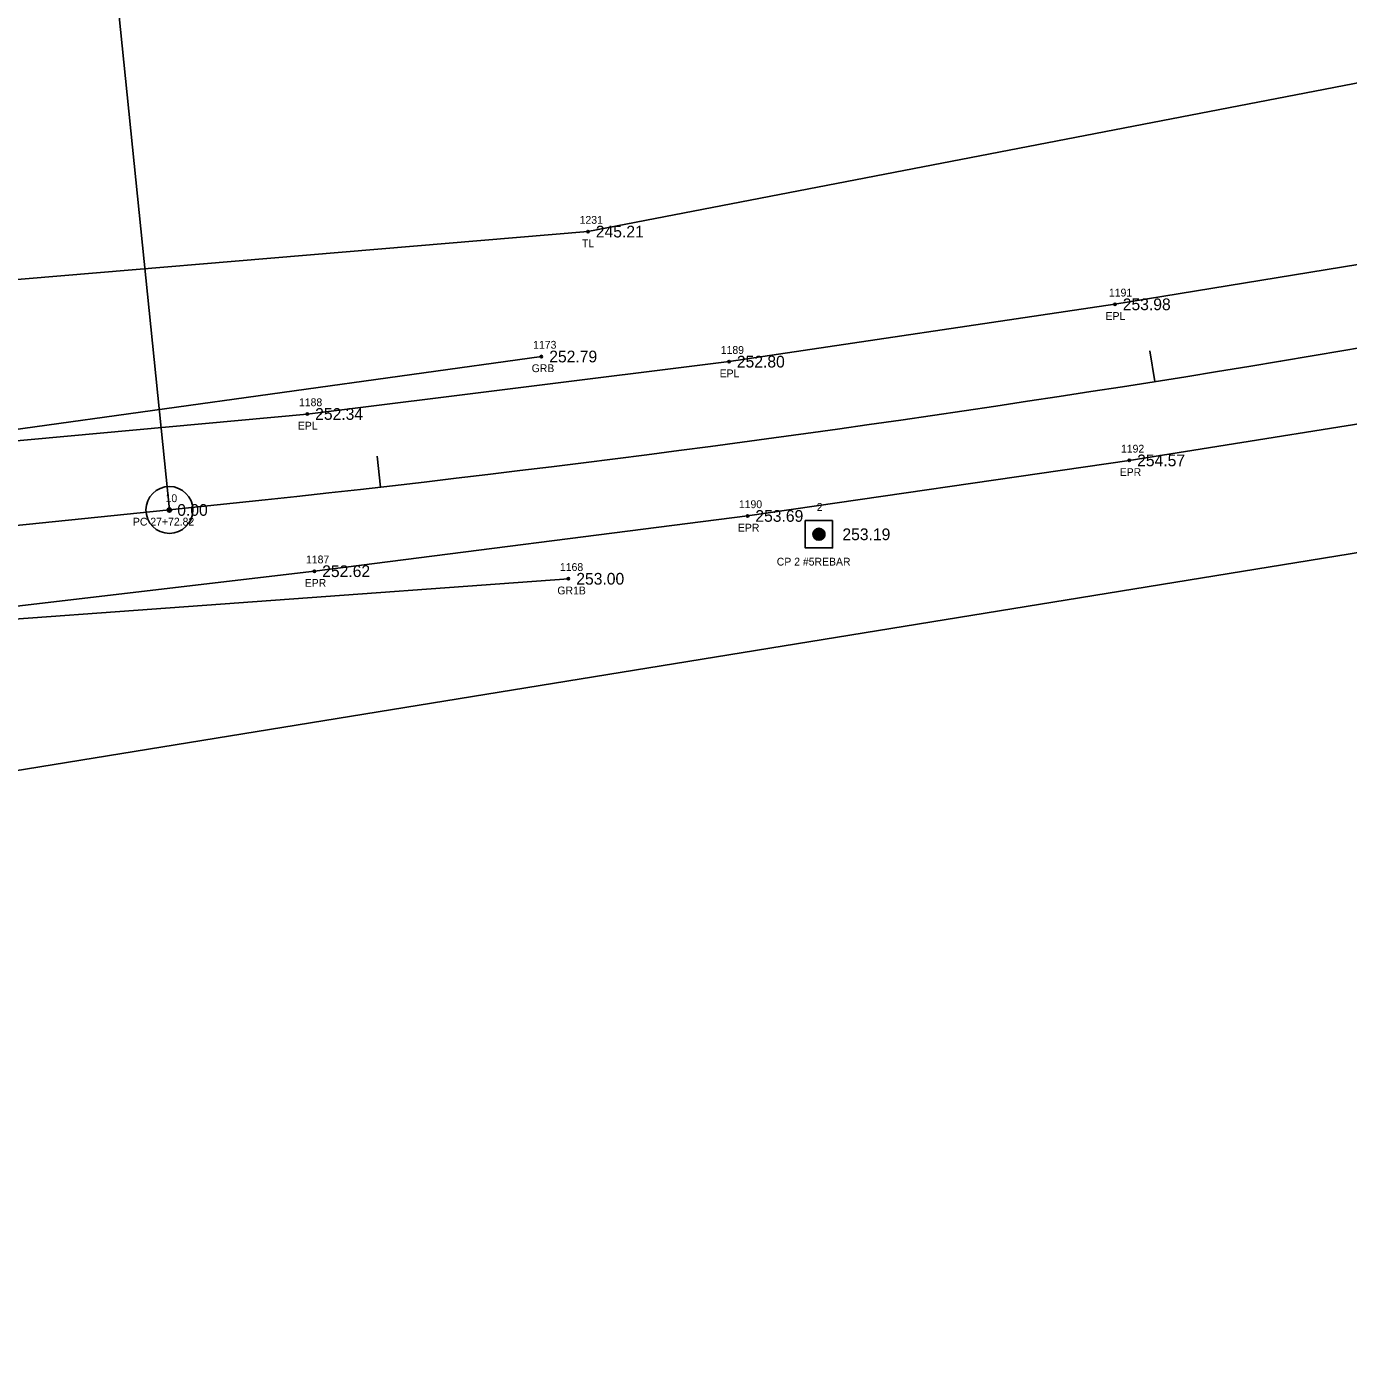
# Model space of a CAD drawing. Extents: x 2274993 to 2278766, y 1075634 to 1076749.
# Drawn here: x 2276396.4 to 2276565.4, y 1075966.5 to 1076138.8 of the extents above; entities that cross this region are included whole.
import ezdxf

# ---------------------------------------------------------------- set-up
doc = ezdxf.new("R2010")
doc.units = 0
for name, color, linetype in [('RD_EX_GuardRail', 7, 'Continuous'), ('RD_EX_GuardRail_txCode', 7, 'Continuous'), ('RD_EX_Road', 7, 'Continuous'), ('RD_EX_Road_txCode', 7, 'Continuous'), ('RD_EX_TX_GuardRail_ELEV', 7, 'Continuous'), ('RD_EX_TX_Road_ELEV', 7, 'Continuous'), ('RD_EX_TX_VEG_ELEV', 7, 'Continuous'), ('RD_EX_VEG', 7, 'Continuous'), ('RD_EX_VEG_txCode', 7, 'Continuous'), ('RD_HC_Cl', 7, 'Continuous'), ('RD_HC_Data', 7, 'Continuous'), ('RD_HC_Data_Tic', 7, 'Continuous'), ('RD_HC_Survey', 7, 'Continuous'), ('RD_HC_Survey_ELEV', 7, 'Continuous'), ('RD_HC_Survey_txCode', 7, 'Continuous'), ('RD_HC_txCode', 7, 'Continuous'), ('RD_SMD_Locator', 7, 'Continuous')]:
    doc.layers.add(name, color=color, linetype=linetype)

msp = doc.modelspace()

# ---------------------------------------------------------------- linework, layer by layer
at = {"layer": 'RD_EX_GuardRail'}
for points in [[(2276235.72, 1076070.41), (2276318.74, 1076078.74), (2276379.22, 1076085.12), (2276462.21, 1076096.64)], [(2276238.11, 1076044.54), (2276321.32, 1076055.79), (2276381.25, 1076062.04), (2276465.67, 1076068.19)]]:
    msp.add_lwpolyline(points, dxfattribs=at)
at = {"layer": 'RD_EX_Road'}
for points in [[(2276379.21, 1076084.39), (2276432.25, 1076089.28), (2276486.22, 1076095.98), (2276535.61, 1076103.32), (2276577.16, 1076110.11), (2276620.86, 1076117.78), (2276666.21, 1076126.9), (2276712, 1076137.22), (2276761.13, 1076149.72), (2276804.56, 1076161.71), (2276851.24, 1076175.53), (2276896.93, 1076190.53), (2276950.19, 1076208.22), (2276997.45, 1076224.3), (2277053.81, 1076243.77), (2277132.14, 1076270.77)], [(2276381.27, 1076063.04), (2276433.15, 1076069.16), (2276488.59, 1076076.23), (2276537.45, 1076083.34), (2276579.64, 1076090.09), (2276624.07, 1076098.24), (2276670.54, 1076107.46), (2276716.67, 1076118.09), (2276765.18, 1076130.28), (2276809.58, 1076142.25), (2276856.93, 1076156.58), (2276903.53, 1076171.63), (2276957.27, 1076189.46), (2277005.85, 1076206.01), (2277060.98, 1076225.07), (2277139.5, 1076252.36)]]:
    msp.add_lwpolyline(points, dxfattribs=at)
at = {"layer": 'RD_EX_VEG'}
for points in [[(2276059.59, 1076114.41), (2276109.62, 1076078.55), (2276326.54, 1076098.1), (2276364.64, 1076103.94), (2276468.17, 1076112.63), (2276687.38, 1076155.02), (2276867.98, 1076201.61), (2276854.55, 1076228.93)], [(2275588.01, 1075931.75), (2275680.64, 1075961.35), (2275730.55, 1075971.06), (2275824.32, 1075986.29), (2275869.68, 1075991.08), (2276385.92, 1076042.16), (2276665.98, 1076087.69), (2276721.29, 1076100.17), (2276841.99, 1076132.87), (2276855.5, 1076106.15)]]:
    msp.add_lwpolyline(points, dxfattribs=at)
at = {"layer": 'RD_HC_Cl'}
msp.add_line((2275853.33, 1076019.72), (2276414.6, 1076077), dxfattribs=at)
msp.add_arc((2276181.89, 1078357), 2291.84, 275.82778, 288.94274, dxfattribs=at)
at = {"layer": 'RD_HC_Data'}
msp.add_line((2276414.6, 1076077), (2276402.77, 1076192.97), dxfattribs=at)
for radius in [3, 0.282]:
    msp.add_circle((2276414.6, 1076077), radius, dxfattribs=at)
at = {"layer": 'RD_HC_Data_Tic'}
for p, q in [((2276540.7, 1076093.42), (2276540.07, 1076097.37)), ((2276441.62, 1076079.92), (2276441.17, 1076083.9))]:
    msp.add_line(p, q, dxfattribs=at)
at = {"layer": 'RD_HC_Survey'}
for p, q in [((2276496.98, 1076073.7), (2276496.98, 1076074.06)), ((2276497.01, 1076073.62), (2276497.01, 1076074.14)), ((2276497.03, 1076073.56), (2276497.03, 1076074.2)), ((2276497.06, 1076073.51), (2276497.06, 1076074.25)), ((2276497.08, 1076073.47), (2276497.08, 1076074.29)), ((2276497.11, 1076073.43), (2276497.11, 1076074.33)), ((2276497.13, 1076073.4), (2276497.13, 1076074.36)), ((2276497.16, 1076073.37), (2276497.16, 1076074.39)), ((2276497.18, 1076073.34), (2276497.18, 1076074.42)), ((2276497.21, 1076073.32), (2276497.21, 1076074.44)), ((2276497.23, 1076073.3), (2276497.23, 1076074.46)), ((2276497.26, 1076073.27), (2276497.26, 1076074.48)), ((2276497.28, 1076073.26), (2276497.28, 1076074.5)), ((2276497.31, 1076073.24), (2276497.31, 1076074.52)), ((2276497.33, 1076073.22), (2276497.33, 1076074.54)), ((2276497.36, 1076073.21), (2276497.36, 1076074.55)), ((2276497.38, 1076073.2), (2276497.38, 1076074.56)), ((2276497.4, 1076073.18), (2276497.4, 1076074.58)), ((2276497.43, 1076073.17), (2276497.43, 1076074.59)), ((2276497.45, 1076073.16), (2276497.45, 1076074.6)), ((2276497.48, 1076073.15), (2276497.48, 1076074.61)), ((2276497.5, 1076073.14), (2276497.5, 1076074.61)), ((2276497.53, 1076073.14), (2276497.53, 1076074.62)), ((2276497.55, 1076073.13), (2276497.55, 1076074.63)), ((2276497.58, 1076073.13), (2276497.58, 1076074.63)), ((2276497.6, 1076073.12), (2276497.6, 1076074.64)), ((2276497.63, 1076073.12), (2276497.63, 1076074.64)), ((2276497.65, 1076073.11), (2276497.65, 1076074.64)), ((2276497.68, 1076073.11), (2276497.68, 1076074.65)), ((2276497.7, 1076073.11), (2276497.7, 1076074.65)), ((2276497.73, 1076073.11), (2276497.73, 1076074.65)), ((2276497.75, 1076073.11), (2276497.75, 1076074.65)), ((2276497.78, 1076073.11), (2276497.78, 1076074.65)), ((2276497.8, 1076073.11), (2276497.8, 1076074.65)), ((2276497.83, 1076073.12), (2276497.83, 1076074.64)), ((2276497.85, 1076073.12), (2276497.85, 1076074.64)), ((2276497.88, 1076073.12), (2276497.88, 1076074.64)), ((2276497.9, 1076073.13), (2276497.9, 1076074.63)), ((2276497.92, 1076073.13), (2276497.92, 1076074.62)), ((2276497.95, 1076073.14), (2276497.95, 1076074.62)), ((2276497.97, 1076073.15), (2276497.97, 1076074.61)), ((2276498, 1076073.16), (2276498, 1076074.6)), ((2276498.02, 1076073.17), (2276498.02, 1076074.59)), ((2276498.05, 1076073.18), (2276498.05, 1076074.58)), ((2276498.07, 1076073.19), (2276498.07, 1076074.57)), ((2276498.1, 1076073.2), (2276498.1, 1076074.56)), ((2276498.12, 1076073.22), (2276498.12, 1076074.54)), ((2276498.15, 1076073.23), (2276498.15, 1076074.53)), ((2276498.17, 1076073.25), (2276498.17, 1076074.51)), ((2276498.2, 1076073.27), (2276498.2, 1076074.49)), ((2276498.22, 1076073.29), (2276498.22, 1076074.47)), ((2276498.25, 1076073.31), (2276498.25, 1076074.45)), ((2276498.27, 1076073.33), (2276498.27, 1076074.43)), ((2276498.3, 1076073.36), (2276498.3, 1076074.4)), ((2276498.32, 1076073.38), (2276498.32, 1076074.38)), ((2276498.35, 1076073.41), (2276498.35, 1076074.34)), ((2276498.37, 1076073.45), (2276498.37, 1076074.31)), ((2276498.39, 1076073.49), (2276498.39, 1076074.27)), ((2276498.42, 1076073.53), (2276498.42, 1076074.23)), ((2276498.44, 1076073.59), (2276498.44, 1076074.17)), ((2276498.47, 1076073.66), (2276498.47, 1076074.1)), ((2276498.49, 1076073.77), (2276498.49, 1076073.99))]:
    msp.add_line(p, q, dxfattribs=at)
msp.add_lwpolyline([(2276499.48, 1076075.63), (2276495.98, 1076075.63), (2276495.98, 1076072.13), (2276499.48, 1076072.13)], close=True, dxfattribs=at)
msp.add_circle((2276497.73, 1076073.88), 0.769, dxfattribs=at)
at = {"layer": 'RD_SMD_Locator'}
for centre in [(2276468.17, 1076112.63), (2276535.61, 1076103.32), (2276462.21, 1076096.64), (2276486.22, 1076095.98), (2276432.25, 1076089.28), (2276537.45, 1076083.34), (2276414.6, 1076077), (2276488.59, 1076076.23), (2276497.73, 1076073.88), (2276433.15, 1076069.16), (2276465.67, 1076068.19)]:
    msp.add_circle(centre, 0.15, dxfattribs=at)

# ---------------------------------------------------------------- texts
at = {"layer": 'RD_EX_GuardRail_txCode'}
for s, p in [('1173', (2276461.15, 1076097.64)), ('GRB', (2276460.96, 1076094.64)), ('1168', (2276464.58, 1076069.19)), ('GR1B', (2276464.25, 1076066.19))]:
    msp.add_text(s, height=1, dxfattribs=at).set_placement(p)
at = {"layer": 'RD_EX_Road_txCode'}
for s, p in [('1191', (2276534.84, 1076104.32)), ('EPL', (2276534.41, 1076101.32)), ('1189', (2276485.16, 1076096.98)), ('EPL', (2276485.02, 1076093.98)), ('1188', (2276431.18, 1076090.28)), ('EPL', (2276431.04, 1076087.28)), ('1192', (2276536.38, 1076084.34)), ('EPR', (2276536.22, 1076081.34)), ('1190', (2276487.48, 1076077.23)), ('EPR', (2276487.36, 1076074.23)), ('1187', (2276432.08, 1076070.16)), ('EPR', (2276431.92, 1076067.16))]:
    msp.add_text(s, height=1, dxfattribs=at).set_placement(p)
at = {"layer": 'RD_EX_TX_GuardRail_ELEV'}
for s, p in [('252.79', (2276463.21, 1076095.89)), ('253.00', (2276466.67, 1076067.44))]:
    msp.add_text(s, height=1.5, dxfattribs=at).set_placement(p)
at = {"layer": 'RD_EX_TX_Road_ELEV'}
for s, p in [('253.98', (2276536.61, 1076102.57)), ('252.80', (2276487.22, 1076095.23)), ('252.34', (2276433.25, 1076088.53)), ('254.57', (2276538.45, 1076082.59)), ('253.69', (2276489.59, 1076075.48)), ('252.62', (2276434.15, 1076068.41))]:
    msp.add_text(s, height=1.5, dxfattribs=at).set_placement(p)
at = {"layer": 'RD_EX_TX_VEG_ELEV'}
msp.add_text('245.21', height=1.5, dxfattribs=at).set_placement((2276469.17, 1076111.88))
at = {"layer": 'RD_EX_VEG_txCode'}
for s, p in [('1231', (2276467.1, 1076113.63)), ('TL', (2276467.4, 1076110.63))]:
    msp.add_text(s, height=1, dxfattribs=at).set_placement(p)
at = {"layer": 'RD_HC_Survey_ELEV'}
for s, p in [('0.00', (2276415.6, 1076076.25)), ('253.19', (2276500.73, 1076073.13))]:
    msp.add_text(s, height=1.5, dxfattribs=at).set_placement(p)
at = {"layer": 'RD_HC_Survey_txCode'}
for s, p in [('2', (2276497.45, 1076076.88)), ('CP 2 #5REBAR', (2276492.33, 1076069.88))]:
    msp.add_text(s, height=1, dxfattribs=at).set_placement(p)
at = {"layer": 'RD_HC_txCode'}
for s, p in [('10', (2276414.11, 1076078)), ('PC 27+72.82', (2276409.93, 1076075))]:
    msp.add_text(s, height=1, dxfattribs=at).set_placement(p)

doc.saveas('drawing.dxf')
